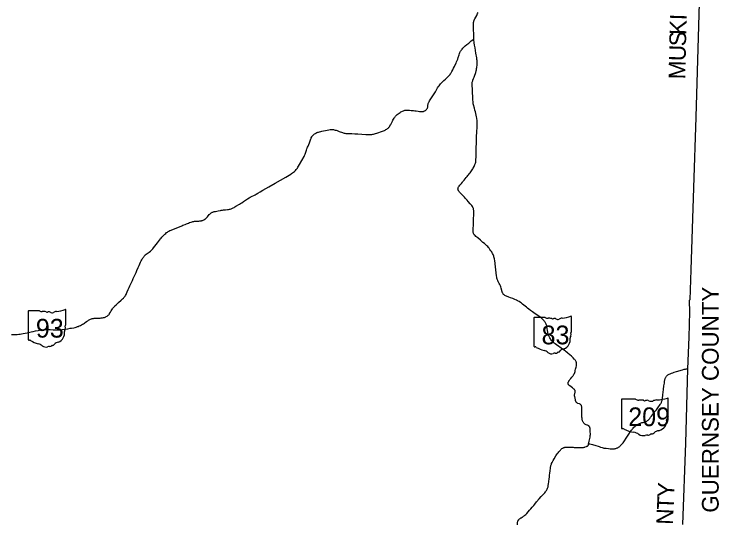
# Model space of a CAD drawing. Extents: x 2015843 to 2287843, y 623733 to 799733.
# Drawn here: x 2161112 to 2203288, y 737859 to 768366 of the extents above; entities that cross this region are included whole.
import ezdxf

# ---------------------------------------------------------------- set-up
doc = ezdxf.new("R2010")
doc.units = 0
for name, color, linetype in [('GM_X_County', 7, 'Continuous'), ('GM_X_County_Text', 7, 'Continuous'), ('GM_X_State_Location', 7, 'Continuous'), ('GM_X_State_Route', 7, 'Continuous'), ('GM_X_State_Shield', 7, 'Continuous')]:
    doc.layers.add(name, color=color, linetype=linetype)

msp = doc.modelspace()

# ---------------------------------------------------------------- linework, layer by layer
at = {"layer": 'GM_X_County'}
msp.add_lwpolyline([(2202153, 770412), (2201913, 762197), (2201774, 757977), (2201599, 753053), (2201548, 751275), (2201535, 751259), (2201527, 751247), (2201523, 751239), (2201518, 751226), (2201514, 751209), (2201511, 751194), (2201509, 751176), (2201509, 751156), (2201510, 751119), (2201511, 751074), (2201513, 751019), (2201516, 750940), (2201524, 750806), (2201531, 750688), (2201534, 750628), (2201532, 750592), (2201531, 750578), (2201529, 750569), (2201526, 750557), (2201479, 749033), (2201419, 747129), (2201296, 742683), (2201102, 737817)], dxfattribs=at)
at = {"layer": 'GM_X_State_Route'}
for points in [[(2188669, 768052), (2188682, 768076), (2188793, 768292), (2188847, 768408), (2188873, 768462)], [(2188627, 767954), (2188634, 767973), (2188652, 768018), (2188669, 768052)], [(2188609, 767690), (2188608, 767749), (2188609, 767831), (2188612, 767879), (2188617, 767911), (2188624, 767942), (2188627, 767954)], [(2188628, 766868), (2188628, 766930), (2188609, 767690)], [(2177687, 758798), (2177720, 758820), (2177773, 758860), (2177824, 758901), (2177884, 758956), (2177943, 759014), (2177987, 759061), (2178030, 759112), (2178063, 759154), (2178097, 759205), (2178132, 759261), (2178190, 759360), (2178466, 759842), (2178498, 759905), (2178518, 759946), (2178536, 759990), (2178553, 760036), (2178573, 760100), (2178611, 760224), (2178639, 760305), (2178655, 760346), (2178678, 760410), (2178702, 760467), (2178785, 760667), (2178808, 760728), (2178868, 760893), (2178880, 760924), (2178899, 760969), (2178921, 761012), (2178938, 761040), (2178956, 761067), (2178987, 761105), (2179021, 761140), (2179045, 761162), (2179070, 761182), (2179097, 761201), (2179139, 761226), (2179166, 761240), (2179232, 761273), (2179284, 761291), (2179331, 761305), (2179523, 761352), (2179844, 761420), (2179956, 761443), (2180021, 761453), (2180071, 761458), (2180120, 761459), (2180170, 761456), (2180219, 761451), (2180268, 761443), (2180332, 761428), (2180380, 761415), (2180442, 761394), (2180565, 761348), (2180764, 761272), (2180811, 761256), (2180858, 761243), (2180906, 761232), (2180954, 761224), (2181003, 761219), (2181068, 761216), (2181199, 761215), (2181314, 761212), (2181494, 761205), (2181675, 761196), (2182163, 761171), (2182313, 761166), (2182379, 761165), (2182444, 761167), (2182510, 761171), (2182575, 761179), (2182623, 761187), (2182671, 761198), (2182734, 761215), (2182811, 761241), (2183166, 761368), (2183212, 761385), (2183273, 761410), (2183317, 761430), (2183360, 761454), (2183416, 761488), (2183457, 761515), (2183495, 761545), (2183519, 761567), (2183541, 761591), (2183572, 761628), (2183600, 761668), (2183625, 761710), (2183645, 761750), (2183655, 761769), (2183709, 761886), (2183748, 761960), (2183779, 762018), (2183819, 762088), (2183852, 762143), (2183882, 762185), (2183911, 762224), (2183945, 762263), (2183990, 762310), (2184039, 762355), (2184102, 762405), (2184156, 762446), (2184207, 762480), (2184262, 762515), (2184320, 762546), (2184364, 762567), (2184411, 762586), (2184457, 762603), (2184489, 762612), (2184521, 762619), (2184555, 762624), (2184591, 762626), (2184636, 762627), (2184692, 762625), (2184767, 762619), (2184865, 762607), (2185010, 762590), (2185092, 762580), (2185173, 762568), (2185286, 762552), (2185366, 762542), (2185431, 762535), (2185480, 762533), (2185513, 762533), (2185545, 762535), (2185577, 762540), (2185608, 762547), (2185639, 762557), (2185669, 762569), (2185697, 762584), (2185725, 762601), (2185750, 762620), (2185775, 762642), (2185795, 762663), (2185816, 762690), (2185833, 762718), (2185846, 762744), (2185853, 762762), (2185861, 762793), (2185866, 762824), (2185872, 762886), (2185880, 762937), (2185885, 762969), (2185897, 763012), (2185911, 763048), (2185930, 763089), (2185951, 763126), (2185978, 763171), (2186056, 763292), (2186169, 763471), (2186320, 763720), (2186387, 763833), (2186455, 763945), (2186508, 764029), (2186545, 764083), (2186585, 764135), (2186638, 764198), (2186681, 764245), (2186704, 764271), (2186762, 764330), (2186822, 764387), (2186920, 764474), (2187006, 764549), (2187066, 764605), (2187112, 764652), (2187156, 764700), (2187197, 764751), (2187235, 764804), (2187270, 764859), (2187311, 764930), (2187365, 765032), (2187416, 765134), (2187465, 765238), (2187493, 765297), (2187558, 765430), (2187591, 765505), (2187622, 765580), (2187656, 765673), (2187688, 765766), (2187738, 765922), (2187770, 766015), (2187789, 766061), (2187809, 766106), (2187832, 766150), (2187858, 766192), (2187886, 766233), (2187916, 766272), (2187958, 766323), (2188003, 766370), (2188051, 766416), (2188113, 766469), (2188203, 766542), (2188318, 766635), (2188470, 766759), (2188558, 766833), (2188576, 766846), (2188591, 766856), (2188607, 766862), (2188628, 766868)], [(2188533, 763998), (2188532, 764015), (2188526, 764080), (2188522, 764118), (2188519, 764175), (2188520, 764215), (2188524, 764258), (2188530, 764290), (2188542, 764331), (2188555, 764371), (2188573, 764421), (2188604, 764505), (2188634, 764585), (2188659, 764649), (2188681, 764710), (2188714, 764808), (2188735, 764881), (2188759, 764972), (2188774, 765036), (2188792, 765133), (2188794, 765142), (2188805, 765214), (2188814, 765296), (2188820, 765378), (2188821, 765460), (2188820, 765542), (2188817, 765592), (2188810, 765657), (2188797, 765755), (2188751, 766030), (2188696, 766353), (2188671, 766499), (2188647, 766644), (2188637, 766710), (2188631, 766782), (2188629, 766837), (2188628, 766868)], [(2190345, 751684), (2190342, 751691), (2190323, 751754), (2190266, 751959), (2190242, 752038), (2190220, 752100), (2190201, 752146), (2190180, 752191), (2190149, 752249), (2190087, 752356), (2190068, 752390), (2190051, 752423), (2190037, 752457), (2190020, 752511), (2190009, 752559), (2189996, 752623), (2189984, 752704), (2189898, 753412), (2189896, 753437), (2189894, 753453), (2189874, 753600), (2189856, 753713), (2189844, 753778), (2189828, 753842), (2189814, 753889), (2189797, 753936), (2189778, 753981), (2189750, 754041), (2189727, 754084), (2189693, 754141), (2189647, 754209), (2189590, 754289), (2189539, 754354), (2189497, 754405), (2189452, 754453), (2189405, 754499), (2189345, 754555), (2189258, 754630), (2189170, 754704), (2189020, 754831), (2188857, 754969), (2188745, 755065), (2188697, 755109), (2188674, 755132), (2188653, 755157), (2188634, 755181), (2188620, 755202), (2188606, 755232), (2188599, 755256), (2188592, 755287), (2188587, 755319), (2188584, 755351), (2188584, 755398), (2188584, 755414), (2188586, 755482), (2188595, 755794), (2188605, 756089), (2188615, 756367), (2188620, 756574), (2188619, 756621), (2188613, 756663), (2188607, 756696), (2188598, 756728), (2188587, 756759), (2188568, 756805), (2188552, 756834), (2188535, 756862), (2188507, 756903), (2188467, 756955), (2188413, 757018), (2188294, 757153), (2188217, 757238), (2188127, 757334), (2188060, 757405), (2187905, 757575), (2187771, 757720), (2187750, 757744), (2187738, 757756), (2187729, 757769), (2187718, 757782), (2187709, 757795), (2187701, 757809), (2187693, 757823), (2187687, 757838), (2187682, 757852), (2187678, 757868), (2187675, 757884), (2187674, 757900), (2187674, 757916), (2187676, 757931), (2187678, 757947), (2187682, 757963), (2187692, 757993), (2187707, 758022), (2187724, 758050), (2187743, 758076), (2187795, 758139), (2187880, 758239), (2187944, 758313), (2187972, 758346), (2187987, 758364), (2188039, 758426), (2188174, 758589), (2188226, 758652), (2188267, 758702), (2188298, 758740), (2188351, 758803), (2188403, 758867), (2188453, 758932), (2188491, 758985), (2188526, 759040), (2188560, 759097), (2188592, 759154), (2188637, 759242), (2188665, 759301), (2188691, 759361), (2188708, 759407), (2188723, 759454), (2188734, 759503), (2188743, 759551), (2188749, 759600), (2188752, 759649), (2188758, 759830), (2188760, 759944), (2188766, 760190), (2188772, 760453), (2188776, 760584), (2188779, 760698), (2188780, 760764), (2188787, 760977), (2188805, 761370), (2188814, 761567), (2188820, 761747), (2188822, 761862), (2188821, 761944), (2188816, 762026), (2188809, 762092), (2188801, 762141), (2188786, 762221), (2188764, 762318), (2188718, 762509), (2188689, 762620), (2188657, 762737), (2188603, 762943), (2188593, 762992), (2188586, 763030), (2188580, 763070), (2188579, 763109), (2188576, 763142), (2188573, 763217), (2188562, 763429), (2188553, 763655), (2188550, 763720), (2188545, 763834), (2188541, 763900), (2188538, 763949), (2188533, 763998)], [(2169266, 754183), (2169297, 754209), (2169328, 754235), (2169350, 754258), (2169373, 754282), (2169407, 754319), (2169459, 754382), (2169693, 754678), (2169754, 754755), (2169874, 754911), (2169914, 754963), (2169956, 755014), (2170009, 755076), (2170065, 755135), (2170124, 755192), (2170185, 755246), (2170236, 755287), (2170289, 755325), (2170330, 755352), (2170373, 755376), (2170431, 755407), (2170504, 755442), (2171141, 755703), (2171217, 755733), (2171340, 755780), (2171432, 755815), (2171539, 755856), (2171615, 755886), (2171707, 755920), (2171769, 755939), (2171816, 755952), (2171864, 755963), (2171912, 755971), (2171961, 755977), (2172026, 755982), (2172108, 755984), (2172173, 755985), (2172223, 755988), (2172272, 755994), (2172321, 756002), (2172352, 756010), (2172383, 756021), (2172429, 756040), (2172474, 756061), (2172517, 756085), (2172544, 756103), (2172571, 756123), (2172609, 756155), (2172644, 756190), (2172677, 756227), (2172793, 756365), (2172826, 756401), (2172861, 756435), (2172886, 756456), (2172913, 756474), (2172941, 756490), (2172970, 756505), (2173000, 756517), (2173047, 756532), (2173094, 756544), (2173158, 756557), (2173238, 756573), (2173319, 756588), (2173464, 756617), (2173512, 756626), (2173577, 756637), (2173641, 756646), (2173771, 756660), (2173885, 756672), (2173950, 756680), (2173999, 756689), (2174047, 756701), (2174094, 756716), (2174140, 756734), (2174185, 756754), (2174229, 756777), (2174272, 756801), (2174328, 756835), (2174385, 756868), (2174597, 756991), (2174668, 757033), (2174737, 757077), (2174831, 757143), (2174898, 757190), (2174965, 757236), (2175088, 757317), (2175172, 757367), (2175243, 757406), (2175359, 757464), (2175461, 757516), (2175533, 757554), (2175590, 757587), (2175605, 757596), (2175689, 757646), (2175829, 757731), (2175999, 757830), (2176355, 758033), (2176743, 758251), (2177383, 758616), (2177582, 758731), (2177666, 758783), (2177687, 758798)], [(2160959, 749199), (2161123, 749197), (2161206, 749198), (2161288, 749202), (2161402, 749211), (2161484, 749220), (2161565, 749233), (2161662, 749251), (2161774, 749276), (2161886, 749301), (2162046, 749335), (2162142, 749355), (2162254, 749379), (2162399, 749409), (2162543, 749439), (2162640, 749457), (2162737, 749471), (2162818, 749479), (2162899, 749485), (2163030, 749489), (2163111, 749490), (2163275, 749486), (2163455, 749482), (2163602, 749477), (2163733, 749473), (2163815, 749472), (2163865, 749474), (2163885, 749476), (2163914, 749479), (2163995, 749489), (2164125, 749508), (2164319, 749540), (2164465, 749564), (2164546, 749577), (2164691, 749602), (2164772, 749618), (2164820, 749629), (2164867, 749644), (2164913, 749662), (2164948, 749677), (2165005, 749703), (2165082, 749738), (2165152, 749772), (2165208, 749803), (2165268, 749837), (2165326, 749877), (2165375, 749912), (2165452, 749969), (2165518, 750018), (2165558, 750045), (2165602, 750071), (2165643, 750091), (2165687, 750110), (2165749, 750132), (2165785, 750141), (2165826, 750153), (2165858, 750159), (2165912, 750169), (2165997, 750175), (2166090, 750175), (2166183, 750178), (2166267, 750180), (2166332, 750185), (2166396, 750193), (2166459, 750203), (2166523, 750220), (2166570, 750236), (2166600, 750248), (2166630, 750262), (2166673, 750287), (2166700, 750305), (2166726, 750325), (2166750, 750348), (2166773, 750372), (2166794, 750398), (2166813, 750425), (2166830, 750452), (2166881, 750537), (2166923, 750607), (2166964, 750678), (2166999, 750732), (2167026, 750772), (2167046, 750798), (2167078, 750835), (2167111, 750870), (2167146, 750905), (2167218, 750970), (2167365, 751101), (2167520, 751246), (2167606, 751322), (2167654, 751367), (2167688, 751402), (2167720, 751440), (2167750, 751480), (2167777, 751521), (2167810, 751578), (2167840, 751637), (2167887, 751741), (2167945, 751877), (2168002, 752013), (2168040, 752104), (2168134, 752313), (2168188, 752432), (2168238, 752536), (2168334, 752744), (2168408, 752909), (2168461, 753029), (2168543, 753208), (2168597, 753327), (2168686, 753520), (2168720, 753595), (2168755, 753669), (2168785, 753727), (2168810, 753769), (2168836, 753810), (2168866, 753849), (2168897, 753887), (2168930, 753922), (2168965, 753956), (2169015, 753999), (2169046, 754023), (2169066, 754039), (2169186, 754126), (2169266, 754183)], [(2195494, 742655), (2195504, 742708), (2195523, 742805), (2195576, 743045), (2195588, 743109), (2195594, 743158), (2195598, 743208), (2195598, 743257), (2195593, 743372), (2195589, 743470), (2195582, 743559), (2195579, 743585), (2195573, 743610), (2195566, 743632), (2195561, 743647), (2195553, 743663), (2195545, 743677), (2195534, 743693), (2195519, 743709), (2195496, 743727), (2195480, 743736), (2195457, 743749), (2195432, 743761), (2195406, 743771), (2195345, 743795), (2195300, 743814), (2195272, 743830), (2195246, 743848), (2195222, 743870), (2195201, 743894), (2195182, 743920), (2195165, 743948), (2195151, 743978), (2195133, 744023), (2195123, 744054), (2195115, 744085), (2195105, 744133), (2195099, 744182), (2195092, 744247), (2195087, 744312), (2195084, 744406), (2195083, 744427), (2195084, 744560), (2195082, 744744), (2195082, 744799), (2195081, 744834), (2195076, 744872), (2195071, 744908), (2195066, 744923), (2195060, 744942), (2195051, 744959), (2195040, 744973), (2195031, 744985), (2195008, 745006), (2194984, 745023), (2194951, 745037), (2194923, 745047), (2194851, 745074), (2194822, 745088), (2194794, 745104), (2194782, 745114), (2194769, 745124), (2194758, 745135), (2194748, 745147), (2194739, 745160), (2194731, 745174), (2194724, 745189), (2194719, 745204), (2194714, 745219), (2194701, 745283), (2194679, 745378), (2194658, 745474), (2194653, 745505), (2194651, 745537), (2194651, 745570), (2194655, 745602), (2194660, 745634), (2194687, 745738), (2194690, 745761), (2194690, 745778), (2194690, 745795), (2194687, 745811), (2194685, 745826), (2194679, 745842), (2194674, 745854), (2194666, 745871), (2194656, 745887), (2194644, 745901), (2194619, 745926), (2194594, 745948), (2194529, 745998), (2194450, 746056), (2194370, 746114), (2194328, 746149), (2194302, 746177), (2194293, 746190), (2194283, 746207), (2194277, 746222), (2194272, 746237), (2194269, 746252), (2194267, 746268), (2194267, 746284), (2194269, 746299), (2194272, 746315), (2194276, 746331), (2194286, 746361), (2194300, 746390), (2194315, 746419), (2194341, 746460), (2194370, 746499), (2194422, 746562), (2194487, 746635), (2194541, 746697), (2194571, 746736), (2194589, 746763), (2194615, 746812), (2194638, 746856), (2194662, 746919), (2194679, 746975), (2194696, 747038), (2194715, 747118), (2194739, 747231), (2194757, 747327), (2194766, 747382), (2194770, 747425), (2194770, 747457), (2194767, 747480), (2194763, 747503), (2194762, 747510), (2194752, 747543), (2194740, 747571), (2194726, 747603), (2194710, 747631), (2194692, 747657), (2194665, 747688), (2194632, 747724), (2194566, 747790), (2194459, 747893), (2194363, 747982), (2194277, 748058), (2194228, 748101), (2194151, 748163), (2194085, 748212), (2193924, 748325), (2193762, 748438), (2193709, 748475), (2193562, 748580), (2193483, 748637), (2193431, 748678), (2193394, 748710), (2193362, 748740), (2193324, 748778), (2193292, 748815), (2193275, 748839), (2193232, 748896), (2193204, 748938), (2193168, 748997), (2193125, 749076), (2193117, 749096), (2193098, 749141), (2193081, 749192), (2193069, 749243), (2193057, 749304), (2193031, 749455), (2193018, 749536), (2192998, 749649), (2192989, 749689), (2192984, 749713), (2192971, 749761), (2192954, 749808), (2192935, 749853), (2192912, 749897), (2192886, 749939), (2192858, 749980), (2192827, 750019), (2192794, 750056), (2192758, 750090), (2192721, 750123), (2192669, 750163), (2192564, 750242), (2192298, 750434), (2192125, 750559), (2192019, 750636), (2191914, 750714), (2191834, 750772), (2191769, 750822), (2191693, 750889), (2191625, 750949), (2191544, 751017), (2191485, 751061), (2191414, 751113), (2191337, 751161), (2191242, 751215), (2191169, 751250), (2191079, 751291), (2190959, 751343), (2190821, 751397), (2190714, 751437), (2190574, 751486), (2190513, 751509), (2190484, 751523), (2190456, 751539), (2190431, 751559), (2190408, 751581), (2190387, 751606), (2190369, 751633), (2190354, 751661), (2190345, 751684)], [(2195494, 742655), (2195504, 742655), (2195519, 742654), (2195538, 742653), (2195574, 742646), (2195643, 742632), (2195730, 742607), (2195778, 742595), (2195857, 742572), (2196115, 742487), (2196212, 742455), (2196306, 742425), (2196358, 742412), (2196403, 742401), (2196452, 742393), (2196533, 742383), (2196673, 742366), (2196778, 742359), (2196864, 742355), (2196934, 742352), (2196991, 742352), (2197032, 742356), (2197050, 742357), (2197080, 742363), (2197116, 742373), (2197153, 742386), (2197193, 742402), (2197203, 742407), (2197234, 742421), (2197281, 742450), (2197311, 742471), (2197354, 742501), (2197388, 742529), (2197428, 742565), (2197462, 742601), (2197500, 742643), (2197552, 742707), (2197595, 742768), (2197643, 742835), (2197743, 742985), (2197861, 743162), (2197907, 743231), (2198004, 743382), (2198058, 743464), (2198096, 743518), (2198126, 743557), (2198158, 743594), (2198204, 743642), (2198252, 743686), (2198302, 743729), (2198368, 743779), (2198409, 743807), (2198451, 743832), (2198495, 743855), (2198540, 743875), (2198587, 743893), (2198634, 743908), (2198682, 743920), (2198755, 743935), (2198816, 743949), (2198865, 743962), (2198899, 743972), (2198936, 743986), (2198968, 744005), (2198996, 744023), (2199023, 744042), (2199048, 744063), (2199074, 744089), (2199108, 744126), (2199146, 744173), (2199198, 744247), (2199249, 744311), (2199306, 744388), (2199367, 744466), (2199454, 744577), (2199498, 744631), (2199547, 744687), (2199589, 744738), (2199676, 744859), (2199735, 744936), (2199782, 745002), (2199803, 745037), (2199827, 745080), (2199847, 745124), (2199860, 745157), (2199874, 745202), (2199888, 745264), (2199905, 745342), (2199920, 745426), (2199931, 745514), (2199940, 745578), (2199977, 745911), (2200002, 746125), (2200023, 746274), (2200036, 746388), (2200040, 746420), (2200049, 746468), (2200050, 746474), (2200057, 746501), (2200066, 746532), (2200076, 746561), (2200095, 746603), (2200109, 746632), (2200130, 746666), (2200152, 746696), (2200176, 746723), (2200183, 746730), (2200200, 746747), (2200232, 746771), (2200267, 746793), (2200311, 746817), (2200378, 746848), (2200452, 746878), (2200528, 746905), (2200607, 746931), (2200754, 746977), (2201109, 747082), (2201215, 747113), (2201253, 747122), (2201284, 747126), (2201325, 747129), (2201361, 747129), (2201404, 747128), (2201420, 747126)], [(2193182, 741027), (2193202, 741190), (2193214, 741270), (2193223, 741318), (2193232, 741350), (2193248, 741396), (2193266, 741441), (2193280, 741470), (2193309, 741529), (2193370, 741644), (2193427, 741744), (2193539, 741925), (2193619, 742049), (2193666, 742116), (2193706, 742168), (2193748, 742218), (2193803, 742278), (2193838, 742313), (2193874, 742346), (2193899, 742366), (2193925, 742385), (2193953, 742401), (2193982, 742415), (2194012, 742427), (2194043, 742436), (2194075, 742442), (2194107, 742446), (2194139, 742448), (2194171, 742449), (2194236, 742448), (2194417, 742445), (2194449, 742444), (2194564, 742442), (2194629, 742440), (2194712, 742437), (2194760, 742435), (2194858, 742431), (2195038, 742425), (2195071, 742424), (2195104, 742425), (2195137, 742428), (2195186, 742436), (2195217, 742445), (2195256, 742455), (2195282, 742462), (2195364, 742490), (2195393, 742503), (2195423, 742517), (2195439, 742526), (2195452, 742539), (2195455, 742543), (2195462, 742552), (2195470, 742565), (2195476, 742580), (2195482, 742596), (2195486, 742611), (2195494, 742655)], [(2191229, 737803), (2191235, 737885), (2191240, 737934), (2191246, 737967), (2191253, 737999), (2191258, 738015), (2191262, 738026), (2191266, 738035), (2191278, 738060), (2191295, 738089), (2191305, 738102), (2191316, 738115), (2191328, 738127), (2191334, 738133), (2191356, 738153), (2191394, 738184), (2191445, 738214), (2191462, 738225), (2191515, 738255), (2191563, 738286), (2191597, 738313), (2191636, 738343), (2191674, 738375), (2191734, 738431), (2191791, 738490), (2191880, 738587), (2191957, 738672), (2192043, 738770), (2192119, 738857), (2192214, 738969), (2192267, 739032), (2192381, 739172), (2192541, 739359), (2192659, 739495), (2192735, 739581), (2192790, 739642), (2192866, 739727), (2192909, 739777), (2192939, 739816), (2192968, 739857), (2192993, 739899), (2193016, 739943), (2193035, 739989), (2193051, 740036), (2193063, 740084), (2193080, 740164), (2193096, 740261), (2193111, 740375), (2193117, 740424), (2193128, 740538), (2193144, 740685), (2193154, 740782), (2193168, 740896), (2193182, 741027)]]:
    msp.add_lwpolyline(points, dxfattribs=at)
at = {"layer": 'GM_X_State_Shield'}
for p, q in [((2161960, 750589), (2161960, 748888)), ((2162639, 750618), (2161982, 750618)), ((2164201, 749771), (2164201, 750661)), ((2192222, 750187), (2192222, 748486)), ((2192901, 750216), (2192244, 750216)), ((2194464, 749369), (2194464, 750258)), ((2164201, 749771), (2164201, 749771)), ((2194463, 749369), (2194464, 749369)), ((2197451, 745290), (2197451, 743589)), ((2198299, 745320), (2197478, 745320)), ((2200252, 744472), (2200252, 745362)), ((2200252, 744472), (2200252, 744472))]:
    msp.add_line(p, q, dxfattribs=at)
for centre, radius, start, end in [((2161986, 750593), 26, 98.1301, 188.1301), ((2162795, 750816), 252, 231.6195, 271.1119), ((2162878, 749663), 904, 80.4867, 94.9883), ((2163084, 750602), 72.7, 219.7921, 297.1024), ((2163190, 750405), 151, 54.4667, 119.1411), ((2163385, 750675), 182, 233.8562, 294.8282), ((2163706, 750099), 478, 97.3462, 120.7689), ((2163403, 752938), 2377, 275.8445, 288.9065), ((2164177, 750664), 25, 351.8621, 97.738), ((2192248, 750191), 26, 98.1301, 188.1301), ((2193057, 750414), 252, 231.6195, 271.1119), ((2193141, 749261), 904, 80.4867, 94.9883), ((2193346, 750199), 72.7, 219.7921, 297.1024), ((2193452, 750003), 151, 54.4667, 119.1411), ((2193647, 750273), 182, 233.8562, 294.8282), ((2193968, 749697), 478, 97.3462, 120.7689), ((2193665, 752536), 2377, 275.8445, 288.9065), ((2194439, 750262), 25, 351.8621, 97.738), ((2164291, 749398), 169, 136.8065, 186.9296), ((2164196, 749705), 38.6, 107.944, 210.337), ((2163950, 749593), 232, 340.033, 23.6496), ((2164175, 749767), 26.7, 289.6038, 7.7341), ((2163536, 749285), 595, 292.3089, 8.9858), ((2194553, 748996), 169, 136.8065, 186.9296), ((2194458, 749303), 38.6, 107.944, 210.337), ((2194212, 749191), 232, 340.033, 23.6496), ((2194437, 749365), 26.7, 289.6038, 7.7341), ((2161986, 748884), 26.2, 171.9584, 258.3066), ((2161990, 749058), 200, 267.339, 280.6039), ((2162031, 748790), 72.1, 29.7484, 93.2717), ((2162941, 750318), 1716, 240.4129, 257.1985), ((2162429, 748124), 537, 47.1842, 75.836), ((2163787, 748410), 326, 94.4031, 142.5768), ((2193798, 748883), 595, 292.3089, 8.9858), ((2163010, 748781), 341, 230.7004, 286.2918), ((2163207, 748193), 280, 85.6951, 111.2099), ((2163232, 748654), 182, 268.777, 315.5493), ((2163396, 748489), 51.1, 65.7517, 132.6484), ((2163374, 748723), 192, 282.8732, 323.2771), ((2192248, 748482), 26.2, 171.9584, 258.3066), ((2192252, 748656), 200, 267.339, 280.6039), ((2192293, 748388), 72.1, 29.7484, 93.2717), ((2193203, 749916), 1716, 240.4129, 257.1985), ((2192691, 747722), 537, 47.1842, 75.836), ((2193637, 748321), 192, 282.8732, 323.2771), ((2194049, 748008), 326, 94.4031, 142.5768), ((2193272, 748379), 341, 230.7004, 286.2918), ((2193469, 747791), 280, 85.6951, 111.2099), ((2193494, 748252), 182, 268.777, 315.5493), ((2193658, 748087), 51.1, 65.7517, 132.6484)]:
    msp.add_arc(centre, radius, start, end, dxfattribs=at)
for centre, major_axis, start_param, end_param in [((2197483, 745294), (32.5, 0), 1.712693, 3.28349), ((2198494, 745517), (315, 0), 4.042523, 4.731795), ((2198598, 744365), (1130, 0), 1.404758, 1.657858), ((2198855, 745303), (90.8, 0), 3.836095, 5.185415), ((2198988, 745106), (189, 0), 0.950623, 2.079405), ((2199633, 744800), (598, 0), 1.699011, 2.107814), ((2199254, 747639), (2971, 0), 4.814394, 5.042369), ((2200221, 745365), (31.2, 0), 6.141152, 7.989035), ((2199232, 745376), (227, 0), 4.081561, 5.145723), ((2200245, 744407), (48.3, 0), 1.883978, 3.671073), ((2200219, 744468), (33.4, 0), 5.05454, 6.418171), ((2199421, 743986), (743, 0), 5.101752, 6.440018), ((2200364, 744099), (211, 0), 2.387724, 3.262537), ((2199938, 744294), (290, 0), 5.934695, 6.695948), ((2197483, 743585), (32.7, 0), 3.00124, 4.508301), ((2197539, 743491), (90.1, 0), 0.519207, 1.627899), ((2197488, 743759), (250, 0), 4.665946, 4.897461), ((2198677, 745019), (2146, 0), 4.195997, 4.488961), ((2198037, 742825), (671, 0), 0.823519, 1.323587), ((2198763, 743483), (426, 0), 4.026481, 4.996735), ((2199009, 742894), (350, 0), 1.495662, 1.94098), ((2199040, 743355), (227, 0), 4.691044, 5.507374), ((2199246, 743190), (63.9, 0), 1.147584, 2.315152), ((2199218, 743424), (240, 0), 4.937069, 5.64225), ((2199734, 743112), (407, 0), 1.647645, 2.488434)]:
    msp.add_ellipse(centre, major_axis=major_axis, ratio=0.8, start_param=start_param, end_param=end_param, dxfattribs=at)

# ---------------------------------------------------------------- texts
at = {"layer": 'GM_X_County_Text'}
for s, rotation, p in [('I', 88.1853, (2201353, 767990)), ('K', 88.5993, (2201332, 767108)), ('S', 88.6929, (2201316, 766431)), ('U', 88.6907, (2201296, 765547)), ('M', 88.692, (2201271, 764460)), ('GUERNSEY COUNTY', 90, (2203274, 738531)), ('Y', 87.501, (2200607, 739425)), ('T', 87.4973, (2200575, 738677)), ('N', 87.5004, (2200536, 737794))]:
    msp.add_text(s, height=1000, rotation=rotation, dxfattribs=at).set_placement(p)
at = {"layer": 'GM_X_State_Location'}
for s, p in [('93', (2182675, 761134)), ('93', (2162439, 749250)), ('83', (2192878, 748779)), ('209', (2198691, 743868))]:
    msp.add_text(s, height=1, rotation=0, dxfattribs=at).set_placement(p)
for s, p in [('s', (2182927, 761207)), ('r', (2182927, 761207)), ('s', (2162691, 749322)), ('r', (2162691, 749322)), ('s', (2193130, 748852)), ('r', (2193130, 748852)), ('s', (2199044, 743941)), ('r', (2199044, 743941))]:
    msp.add_text(s, height=1, dxfattribs=at).set_placement(p)
at = {"layer": 'GM_X_State_Shield'}
for s, p in [('93', (2162416, 749008)), ('83', (2192678, 748606)), ('209', (2197863, 743709))]:
    msp.add_text(s, height=1120.7, dxfattribs=at).set_placement(p)

doc.saveas('drawing.dxf')
